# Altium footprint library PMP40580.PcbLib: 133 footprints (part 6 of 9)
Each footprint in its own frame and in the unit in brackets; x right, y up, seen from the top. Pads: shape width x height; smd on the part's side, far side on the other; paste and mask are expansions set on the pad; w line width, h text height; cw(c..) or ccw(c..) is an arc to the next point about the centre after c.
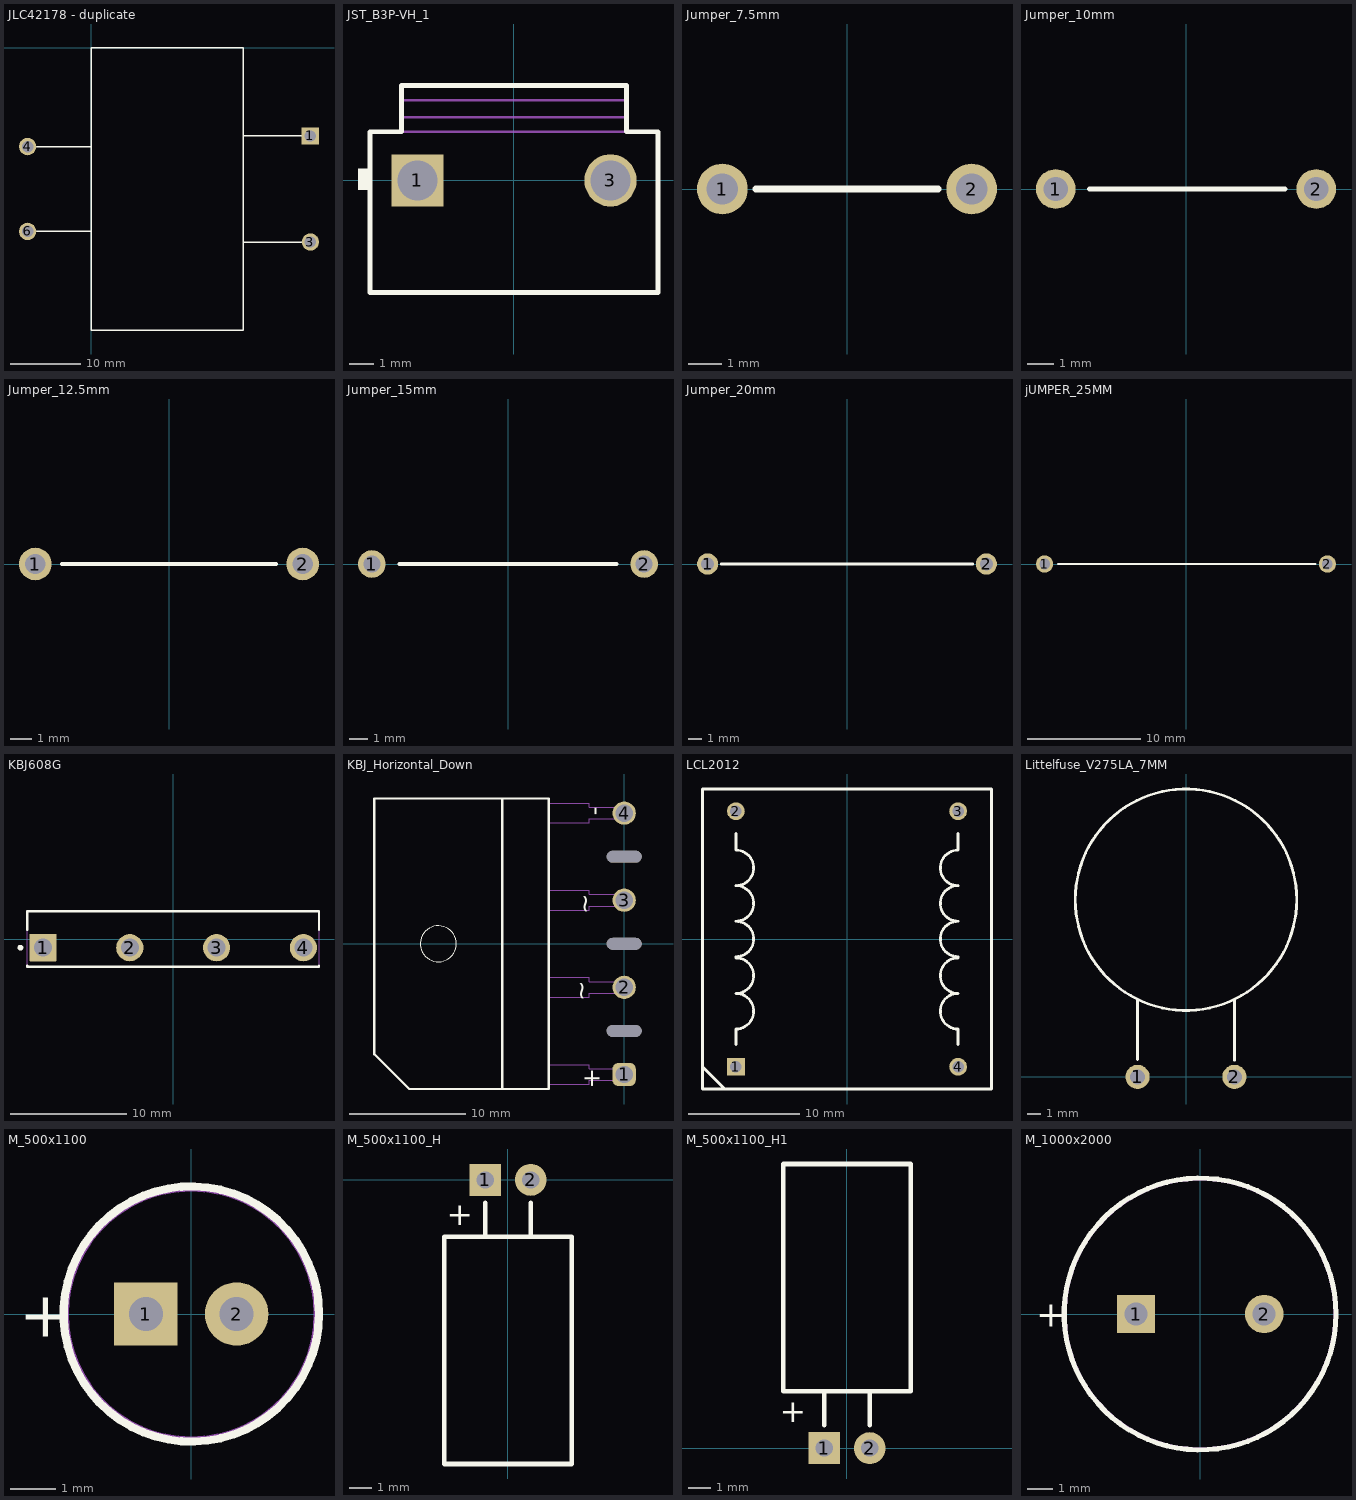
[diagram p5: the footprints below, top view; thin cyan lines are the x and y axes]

## JLC42178 - duplicate [mm]
pads (4):
  rrect4% 2.45x2.45 hole 1.6 paste-1000 mask+0: 1(31,-12.5)
  round 2.45 hole 1.6 paste-1000 mask+0: 3(31,-27.5) 4(-9,-14) 6(-9,-26)
Top Overlay:
  lines w0.2: -9.5,-26 0,-26 ; -9.5,-14 0,-14 ; 21.5,-27.5 31,-27.5 ; 21.5,-12.5 31,-12.5 ; 0,-40 0,0 21.5,0 21.5,-40 0,-40

## JST_B3P-VH_1 [mm] "Header (Shrouded), 3.96mm, 3x1, TH"
height 10.9
pads (2):
  rect 2.15x2.15 hole 1.65: 1(-3.96,0)
  round 2.15 hole 1.65: 3(3.96,0)
Top Overlay:
  rectangle: -6.4,-0.4 -5.9,0.5
  lines w0.2: -5.91,-4.6 -5.91,2 -4.61,2 -4.61,2.589 -4.61,3.3 -4.61,3.9 4.61,3.9 4.61,3.3 4.61,2.589 4.61,2 5.91,2 5.91,-4.6 -5.91,-4.6
Mechanical 5:
  lines w0.1: -4.61,2 -5.91,2 -5.91,-4.6 5.91,-4.6 5.91,2 4.61,2 ; -4.61,2 4.61,2 ; -4.61,2 -4.61,2.589 ; -4.61,2.589 4.61,2.589 ; -4.61,2.589 -4.61,3.3 ; -4.61,3.3 -4.61,3.9 4.61,3.9 4.61,3.3 ; -4.61,3.3 4.61,3.3 ; 4.61,2 4.61,2.589 ; 4.61,2.589 4.61,3.3
  text ".Designator" at -1.524,-0.508 h1.02

## Jumper_7.5mm [mil] "Wire jumper, 20mm"
height 255.91
pads (2):
  round 60 hole 37: 1(-147.64,0) 2(147.64,0)
Top Overlay:
  lines w7.87: -108.27,0 108.27,0
Mechanical 5:
  lines w5: -108.27,0 108.27,0
  text ".Designator" at -55.12,-15.75 h30

## Jumper_10mm [mil] "Wire jumper, 10mm"
height 255.91
pads (2):
  round 60 hole 37: 1(-196.85,0) 2(196.85,0)
Top Overlay:
  lines w7.87: -145.67,0 149.61,0
Mechanical 5:
  lines w5: -145.67,0 149.61,0
  text ".Designator" at -55.12,-15.75 h30

## Jumper_12.5mm [mil] "Wire jumper, 12.5mm"
height 255.91
pads (2):
  round 60 hole 37: 1(-246.06,0) 2(246.06,0)
Top Overlay:
  lines w7.87: -196.85,0 196.85,0
Mechanical 5:
  lines w5: -196.85,0 196.85,0
  text ".Designator" at -55.12,-15.75 h30

## Jumper_15mm [mil] "Wire jumper, 15mm"
height 255.91
pads (2):
  round 60 hole 37: 1(-295.28,0) 2(295.28,0)
Top Overlay:
  lines w7.87: -236.22,0 236.22,0
Mechanical 5:
  lines w5: -236.22,0 236.22,0
  text ".Designator" at -55.12,-15.75 h30

## Jumper_20mm [mil] "Wire jumper, 20mm"
height 255.91
pads (2):
  round 60 hole 37: 1(-393.7,0) 2(393.7,0)
Top Overlay:
  lines w7.87: -355,0 355,0
Mechanical 5:
  lines w5: -355,0 355,0
  text ".Designator" at -55.12,-15.75 h30

## jUMPER_25MM [mil] "Wire jumper, 25mm"
height 255.91
pads (2):
  round 60 hole 37: 1(-492.13,0) 2(492.13,0)
Top Overlay:
  lines w7.87: -445,0 450,0
Mechanical 5:
  lines w5: -445,0 450,0
  text ".Designator" at -55.12,-15.75 h30

## KBJ608G [mm]
pads (4):
  rrect4% 2.35x2.35 hole 1.55 paste-1000 mask+0: 1(-11.25,-0.75)
  round 2.35 hole 1.55 paste-1000 mask+0: 2(-3.75,-0.75) 3(3.75,-0.75) 4(11.25,-0.75)
Top Overlay:
  circle w0.25: c-13.2,-0.75 r0.125
  lines w0.2: -12.6,-2.3 -12.6,-2.4 12.6,-2.4 12.6,-2.3 ; -12.6,0.8 -12.6,2.4 12.6,2.4 12.6,0.8
Mechanical 5:
  lines w0.1: -12.6,-2.4 12.6,-2.4 12.6,2.4 -12.6,2.4 -12.6,-2.4
  text ".Designator" at 0,0 h0.5
3D body "Diode_KBJ608G_KBJ.STEP": height 2.3, standoff -2.3, extent -3.75,-12.5 19.25,12.5

## KBJ_Horizontal_Down [mm] "TH, 4-Leads, Body 22.3x18.8mm, Pitch 5.08"
height 5.86
pads (7):
  rrect50% 2x2 hole 1.5: 1(0,-11.25)
  round 2 hole 1.5: 2(0,-3.75) 3(0,3.75) 4(0,11.25)
  oval 3x1 hole 1 slot 3 at 0 deg: ""(0,-7.5) ""(0,0) ""(0,7.5)
Top Overlay:
  circle w0.1: c-16,0 r1.55
  lines w0.2: -10.5,-12.5 -10.5,12.5 ; -21.5,-9.5 -18.5,-12.5 -6.5,-12.5 -6.5,12.5 -21.5,12.5 -21.5,-9.5
  text "-" at -3,11.8 h1.52
  text "~" at -4,4.3 h1.52
  text "~" at -4.3,-3.2 h1.52
  text "+" at -3.4,-10.7 h1.52
Mechanical 5:
  lines w0.1: -6.5,-12.1 -3,-12.1 -3,-11.75 0,-11.75 0,-10.75 -3,-10.75 -3,-10.4 -6.5,-10.4 ; -6.5,-4.6 -3,-4.6 -3,-4.25 0,-4.25 0,-3.25 -3,-3.25 -3,-2.9 -6.5,-2.9 ; -6.5,2.9 -3,2.9 -3,3.25 0,3.25 0,4.25 -3,4.25 -3,4.6 -6.5,4.6 ; -6.5,10.4 -3,10.4 -3,10.75 0,10.75 0,11.75 -3,11.75 -3,12.1 -6.5,12.1
3D body "Diode_KBJ608G_KBJ.STEP": height 4.6, standoff 0, extent -21.5,-12.5 1.5,12.5

## LCL2012 [mm]
pads (4):
  rrect4% 1.6x1.6 hole 1.05 paste-1000 mask+0: 1(-10,-11.5)
  round 1.6 hole 1.05 paste-1000 mask+0: 2(-10,11.5) 3(10,11.5) 4(10,-11.5)
Top Overlay:
  lines w0.254: -13,-11.5 -11,-13.5 ; -10,-9.5 -10,-8.103 ccw(c-10,-6.5) -10,-4.897 ; -10,-4.903 ccw(c-10,-3.3) -10,-1.697 ; -10,-1.603 ccw(c-10,0) -10,1.603 ; -10,1.597 ccw(c-10,3.2) -10,4.803 ; -10,4.797 ccw(c-10,6.4) -10,8.003 -10,9.5 ; 10,-9.5 10,-8.103 cw(c10,-6.5) 10,-4.897 ; 10,-4.903 cw(c10,-3.3) 10,-1.697 ; 10,-1.603 cw(c10,0) 10,1.603 ; 10,1.597 cw(c10,3.2) 10,4.803 ; 10,4.797 cw(c10,6.4) 10,8.003 10,9.5 ; -13,-13.5 -13,13.5 13,13.5 13,-13.5 -13,-13.5

## Littelfuse_V275LA_7MM [mm] "EPCOS"
height 22
pads (2):
  round 1.75 hole 1.1: 1(-3.5,0) 2(3.5,0)
Top Overlay:
  circle w0.2: c0,12.8 r8
  lines w0.2: -3.5,1.25 -3.5,5.55 ; 3.5,1.2 3.5,5.6
Mechanical 5:
  circle w0.1: c0,12.8 r8
  lines w0.1: -3.5,1.25 -3.5,5.55 ; 3.5,1.2 3.5,5.6
  text ".Designator" at -1.9,-0.6 h1.02

## M_500x1100 [mm] "PANASONIC"
height 12
pads (2):
  rect 1.4x1.4 hole 0.75: 1(-1,0)
  round 1.4 hole 0.75: 2(1,0)
Top Overlay:
  circle w0.18: c0,0 r2.816
  text "+" at -3.8,-0.5 h1.02
Mechanical 5:
  circle w0.1: c0,0 r2.75
  text "+" at -3.8,-0.5 h1.02
  text ".Designator" at -1.9,-0.5 h1.02
3D body "M_500x1100.stp": height 12.01, standoff -4, extent -2.728,-2.745 2.75,2.746

## M_500x1100_H [mm] "PANASONIC"
height 12
pads (2):
  rect 1.4x1.4 hole 0.75: 1(-1,0)
  round 1.4 hole 0.75: 2(1,0)
Top Overlay:
  lines w0.2: -1,-2.5 -1,-1 ; 1,-2.5 1,-1 ; -2.8,-12.5 -2.8,-2.5 2.8,-2.5 2.8,-12.5 -2.8,-12.5
  text "+" at -2.7,-2 h1.02
Mechanical 5:
  lines w0.15: -1,-2.5 -1,-1 ; 1,-2.5 1,-1 ; -2.8,-12.5 2.8,-12.5 2.8,-2.5 -2.8,-2.5 -2.8,-12.5
  text "+" at -2.7,-2 h1.02
  text ".Designator" at -1.9,-0.5 h1.02

## M_500x1100_H1 [mm] "PANASONIC"
height 12
pads (2):
  rect 1.4x1.4 hole 0.75: 1(-1,0)
  round 1.4 hole 0.75: 2(1,0)
Top Overlay:
  lines w0.2: -1,1 -1,2.5 ; 1,1 1,2.5 ; -2.8,2.5 -2.8,12.5 2.8,12.5 2.8,2.5 -2.8,2.5
  text "+" at -1.8,2 h1.02
Mechanical 5:
  lines w0.15: -1,1 -1,2.5 ; 1,1 1,2.5 ; -2.8,2.5 2.8,2.5 2.8,12.5 -2.8,12.5 -2.8,2.5
  text "+" at -1.8,2 h1.02
  text ".Designator" at -1.9,-0.5 h1.02

## M_1000x2000 [mm] "Panasonic"
height 22
pads (2):
  rect 1.5x1.5 hole 0.9: 1(-2.5,0)
  round 1.5 hole 0.9: 2(2.5,0)
Top Overlay:
  circle w0.2: c0,0 r5.3
  text "+" at -6.4,-0.5 h1.02
Mechanical 5:
  circle w0.1: c0,0 r5.25
  text ".Designator" at -1.8,-0.6 h1.02
  text "+" at -6.4,-0.5 h1.02
3D body "M_1000x2000.stp": height 22.01, standoff -4, extent -5.209,-5.241 5.24,5.242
